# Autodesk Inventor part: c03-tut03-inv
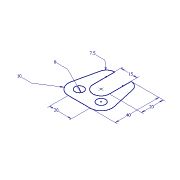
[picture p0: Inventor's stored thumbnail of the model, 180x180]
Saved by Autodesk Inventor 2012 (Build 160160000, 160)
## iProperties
Created: 2010-01
Part Number: c03-tut03-inv
Document SubType Name: Modeling
Designer: CADSoft
Density: 1 g/cm^3
Material: Default
Author: CADSoft
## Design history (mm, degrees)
sketch "Sketch1"
  geometry: L1 (-10, -20)-(10, -20); L2 (19.756, -7.805)-(14.817, 14.146); L3 (7.5, 20)-(7.5, 0); L4 (-7.5, 0)-(-7.5, 20); L5 (-14.817, 14.146)-(-19.756, -7.805); C1 r 4 at (-10, -10); C2 r 4 at (10, -10); A1 r 10 centre (10, -10) between (10, -20) and (19.756, -7.805); A2 r 7.5 centre (7.5, 12.5) between (14.817, 14.146) and (7.5, 20); A3 r 7.5 centre (0, 0) between (-7.5, 0) and (7.5, 0); A4 r 7.5 centre (-7.5, 12.5) between (-7.5, 20) and (-14.817, 14.146); A5 r 10 centre (-10, -10) between (-19.756, -7.805) and (-10, -20); 2 further points
  constraints: 10 end point, 10 point on circle, 8 tangent, 7 centre point, 4 coincident, 3 equal radius, 2 equal length, 2 point on line, 2 vertical, 1 horizontal, 1 other
  dimensions: "d0" = 20 distance of L1.start L1.end; "d1" = 7.5 radius of A4; "d2" = 10 radius of A5; "d3" = 15 distance between parallel lines of L3 L4; "d4" = 20 distance of L3.start L3.end; "d5" = 40 distance from line of L1 L3.start; "d6" = 8 diameter of C1
